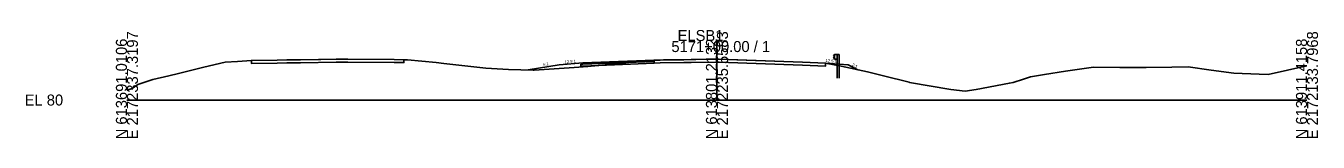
# Model space of a CAD drawing. Extents: x -26 to 1303, y -3010 to 12023.
# Drawn here: x -25.7 to 302.8, y -509.7 to -482.2 of the extents above; entities that cross this region are included whole.
import ezdxf

# ---------------------------------------------------------------- set-up
doc = ezdxf.new("R2010")
doc.units = 0
for name, color, linetype in [('RD_GPK_XS_Cell', 7, 'Continuous'), ('RD_PD_Final_TrvlWay', 7, 'Continuous'), ('RD_XS_Base', 7, 'Continuous'), ('RD_XS_ExGround', 7, 'Continuous'), ('RD_XS_ExPaveRet', 7, 'Continuous'), ('RD_XS_GR', 7, 'Continuous'), ('RD_XS_Greenside', 7, 'Continuous'), ('RD_XS_Pave', 7, 'Continuous'), ('RD_XS_PaveOvlay_CP', 7, 'Continuous'), ('RD_XS_TieSlope', 7, 'Continuous'), ('RD_XS_TX_ShdSlope', 7, 'Continuous'), ('RD_XS_TX_Slope', 7, 'Continuous')]:
    doc.layers.add(name, color=color, linetype=linetype)

msp = doc.modelspace()

# ---------------------------------------------------------------- linework, layer by layer
at = {"layer": 'RD_GPK_XS_Cell'}
for p, q in [((150, -500), (150, -485)), ((0, -500), (150, -500)), ((150, -500), (300, -500))]:
    msp.add_line(p, q, dxfattribs=at)
at = {"layer": 'RD_PD_Final_TrvlWay'}
for p, q in [((180.56, -494.45), (180.56, -490.84)), ((180.56, -490.84), (181.06, -490.88)), ((181.06, -490.88), (181.06, -494.45))]:
    msp.add_line(p, q, dxfattribs=at)
at = {"layer": 'RD_XS_Base'}
for p, q in [((115.39, -490.91), (115.89, -490.89)), ((115.39, -491.41), (115.39, -490.91)), ((115.39, -490.91), (115.39, -490.91)), ((115.89, -491.39), (115.39, -491.41)), ((115.39, -491.41), (115.39, -491.41)), ((115.39, -491.41), (115.39, -491.41)), ((115.89, -490.89), (134.01, -490.17)), ((134.01, -490.67), (115.89, -491.39)), ((115.89, -490.89), (115.89, -490.89)), ((115.89, -491.39), (115.89, -491.39)), ((134.01, -490.6), (134.01, -490.67))]:
    msp.add_line(p, q, dxfattribs=at)
at = {"layer": 'RD_XS_ExGround'}
msp.add_lwpolyline([(0, -497.53), (1.37, -497.06), (2.81, -496.04), (6.62, -494.75), (10.63, -493.86), (13.09, -493.29), (19.58, -491.61), (25.01, -490.34), (28.13, -490.22), (31.67, -489.93), (38.23, -489.85), (41.37, -489.81), (44.1, -489.77), (54.51, -489.61), (67.97, -489.72), (70.4, -489.74), (71.33, -489.81), (78.6, -490.49), (80.59, -490.73), (91.22, -491.94), (96.99, -492.21), (103.25, -492.4), (103.53, -492.41), (113.66, -491.71), (117.16, -491.49), (129.46, -490.29), (131.53, -490.09), (132.86, -489.96), (134.01, -489.85), (135.12, -489.83), (136.42, -489.81), (143.48, -489.71), (150.35, -489.62), (171.77, -490.37), (177.62, -490.61), (181.6, -491.4), (188.26, -492.81), (192.38, -493.87), (198.86, -495.48), (198.92, -495.49), (198.98, -495.51), (209.49, -497.31), (213.09, -497.78), (215.89, -497.36), (224.36, -495.71), (225.29, -495.55), (225.53, -495.5), (227.72, -494.74), (229.68, -494.09), (233.26, -493.52), (238.61, -492.7), (245.76, -491.61), (252.4, -491.75), (254.31, -491.74), (259.08, -491.75), (265.6, -491.62), (269.77, -491.6), (275.65, -492.4), (281.41, -493.14), (287.86, -493.42), (290.13, -493.5), (300, -491.3)], dxfattribs=at)
at = {"layer": 'RD_XS_ExPaveRet'}
for p, q in [((67.97, -489.72), (56.2, -489.62)), ((70.4, -489.74), (67.97, -489.72)), ((70.4, -489.74), (70.4, -489.74)), ((150.35, -489.62), (150.28, -489.62)), ((150.28, -489.62), (150.28, -489.62)), ((150.57, -489.62), (150.35, -489.62)), ((171.77, -490.37), (150.57, -489.62)), ((177.62, -490.61), (177.62, -490.61))]:
    msp.add_line(p, q, dxfattribs=at)
for points in [[(67.97, -489.72), (56.2, -489.62), (54.51, -489.61), (53.21, -489.63), (44.1, -489.77), (42.01, -489.8), (41.37, -489.81), (40.64, -489.82), (38.23, -489.85), (31.67, -489.93), (31.67, -489.93), (31.67, -489.93), (31.67, -490.48), (31.67, -490.68), (31.67, -490.68), (31.67, -490.68), (38.23, -490.6), (40.64, -490.57), (41.37, -490.56), (42.01, -490.55), (44.1, -490.52), (53.21, -490.38), (54.51, -490.36), (56.2, -490.37), (67.97, -490.47), (70.4, -490.49), (70.4, -490.49), (70.4, -489.93), (70.4, -489.74), (70.4, -489.74), (67.97, -489.72)], [(31.67, -489.93), (31.67, -489.93), (31.67, -490.48), (31.67, -490.68), (31.67, -490.68), (38.23, -490.6), (40.64, -490.57), (41.37, -490.56), (42.01, -490.55), (44.1, -490.52), (53.21, -490.38), (54.51, -490.36), (56.2, -490.37), (67.97, -490.47), (70.4, -490.49), (70.4, -490.49), (70.4, -489.93), (70.4, -489.74)], [(41.37, -489.81), (40.64, -489.82), (38.23, -489.85), (38.23, -489.85), (31.67, -489.93)], [(53.21, -489.63), (44.1, -489.77), (42.01, -489.8), (41.37, -489.81)], [(56.2, -489.62), (54.51, -489.61), (53.21, -489.63)], [(177.62, -490.61), (177.62, -491.2), (177.62, -491.36), (177.62, -491.36), (177.62, -491.36), (177.62, -491.36), (171.77, -491.12), (150.57, -490.37), (150.35, -490.37), (150.28, -490.37), (150.21, -490.37), (143.41, -490.46), (141.58, -490.49), (135.57, -490.58), (134.01, -490.6), (134.01, -490.01), (134.01, -489.85), (135.57, -489.83), (141.58, -489.74), (143.41, -489.71), (150.21, -489.62), (150.28, -489.62), (150.35, -489.62), (150.57, -489.62), (171.77, -490.37), (177.62, -490.61), (177.62, -490.61), (177.62, -490.61), (177.62, -490.61)], [(144.63, -489.7), (143.48, -489.71), (143.41, -489.71), (136.42, -489.81), (135.12, -489.83), (134.01, -489.85)], [(134.01, -489.85), (134.01, -490.01), (134.01, -490.6), (135.57, -490.58), (141.58, -490.49), (143.41, -490.46), (150.21, -490.37), (150.28, -490.37), (150.35, -490.37), (150.57, -490.37), (171.77, -491.12), (177.62, -491.36), (177.62, -491.36), (177.62, -491.36), (177.62, -491.2), (177.62, -490.61)], [(150.28, -489.62), (150.21, -489.62), (144.63, -489.7)], [(177.62, -490.61), (177.62, -490.61), (171.77, -490.37)]]:
    msp.add_lwpolyline(points, dxfattribs=at)
at = {"layer": 'RD_XS_GR'}
for p, q in [((179.62, -488.74), (179.82, -488.52)), ((179.69, -488.82), (179.62, -488.74)), ((179.62, -489.32), (179.82, -489.11)), ((179.69, -489.4), (179.62, -489.32)), ((179.89, -489.03), (179.69, -488.82)), ((179.89, -489.61), (179.69, -489.4)), ((179.82, -488.52), (179.89, -488.45)), ((179.82, -489.11), (179.89, -489.03)), ((179.89, -488.45), (179.89, -489.61)), ((180.56, -488.45), (179.89, -488.45)), ((179.89, -488.45), (179.89, -488.75)), ((179.89, -488.75), (179.89, -489.61)), ((180.56, -488.45), (180.56, -490.84)), ((180.81, -488.45), (180.56, -488.45)), ((180.56, -489.61), (180.56, -488.45)), ((181.06, -488.45), (180.81, -488.45)), ((181.06, -490.88), (181.06, -488.45)), ((179.89, -489.61), (180.56, -489.61)), ((180.56, -490.84), (181.06, -490.88))]:
    msp.add_line(p, q, dxfattribs=at)
at = {"layer": 'RD_XS_Greenside'}
for p, q in [((109.89, -491.05), (102.02, -492.36)), ((183.37, -491.07), (185.81, -492.29))]:
    msp.add_line(p, q, dxfattribs=at)
at = {"layer": 'RD_XS_Pave'}
for p, q in [((134.01, -489.85), (115.89, -490.57)), ((134.01, -490.01), (115.89, -490.73)), ((115.89, -490.73), (134.01, -490.01)), ((115.89, -490.89), (134.01, -490.17)), ((115.89, -490.57), (115.89, -490.57)), ((115.89, -490.57), (115.89, -490.73)), ((115.89, -490.73), (115.89, -490.73)), ((115.89, -490.73), (115.89, -490.89)), ((115.89, -490.73), (115.89, -490.73)), ((115.89, -490.73), (115.89, -490.73)), ((115.89, -490.89), (115.89, -490.89)), ((115.89, -490.89), (115.89, -490.89))]:
    msp.add_line(p, q, dxfattribs=at)
at = {"layer": 'RD_XS_PaveOvlay_CP'}
for p in [(134.01, -489.85), (115.89, -490.57)]:
    msp.add_line(p, (115.89, -490.57), dxfattribs=at)
at = {"layer": 'RD_XS_TieSlope'}
for p, q in [((115.89, -490.57), (109.89, -491.05)), ((177.62, -490.61), (183.37, -491.07))]:
    msp.add_line(p, q, dxfattribs=at)

# ---------------------------------------------------------------- texts
at = {"layer": 'RD_GPK_XS_Cell'}
for s, p in [('E 2172337.3197', (2.8, -510)), ('E 2172235.5583', (152.8, -510)), ('E 2172133.7968', (302.8, -510)), ('N 613691.0106', (0, -510)), ('N 613801.2132', (150, -510)), ('N 613911.4158', (300, -510))]:
    msp.add_text(s, height=2.8, rotation=90, dxfattribs=at).set_placement(p)
for s, p in [('ELSB1', (140, -485)), ('5171+00.00 / 1', (138.42, -487.8)), ('EL 80', (-26, -501.4))]:
    msp.add_text(s, height=2.8, dxfattribs=at).set_placement(p)
at = {"layer": 'RD_XS_TX_ShdSlope'}
for rotation, p in [(4.5739, (111.28, -490.69)), (355.4261, (177.58, -490.32))]:
    msp.add_text('12.5:1', height=0.75, rotation=rotation, dxfattribs=at).set_placement(p)
at = {"layer": 'RD_XS_TX_Slope'}
for s, rotation, p in [('6:1', 9.4642, (105.86, -491.35)), ('2:1', 333.4349, (184.23, -491.26))]:
    msp.add_text(s, height=0.75, rotation=rotation, dxfattribs=at).set_placement(p)

doc.saveas('drawing.dxf')
